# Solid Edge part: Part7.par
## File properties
Author: Vicky Raina
Template: Normal.par
Last saved by: MYPC
Revision: 8
Application: Solid Edge
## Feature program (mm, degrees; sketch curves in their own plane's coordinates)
sketch for "unnamed Protrusion 1" plane through (0, 0, 0) normal (0, 0, 1) x-axis (1, 0, 0)
  line (-37.8084, 8.3373) -> (-32.6389, -42.9666)
  arc centre (-23.6843, -42.0643) radius 9 from (-32.6389, -42.9666) to (-23.6843, -51.0643) ccw
  line (-23.6843, -51.0643) -> (23.6843, -51.0643)
  arc centre (23.6843, -42.0643) radius 9 from (32.6389, -42.9666) to (23.6843, -51.0643) cw
  line (37.8084, 8.3373) -> (32.6389, -42.9666)
  arc centre (27.8588, 9.3398) radius 10 from (37.8084, 8.3373) to (28.6379, 19.3094) ccw
  line (28.6379, 19.3094) -> (1.1687, 21.4561)
  arc centre (0, 6.5017) radius 15 from (-1.1687, 21.4561) to (1.1687, 21.4561) cw
  line (-28.6379, 19.3094) -> (-1.1687, 21.4561)
  arc centre (-27.8588, 9.3398) radius 10 from (-37.8084, 8.3373) to (-28.6379, 19.3094) cw
extrude "unnamed Protrusion 1" add finite 3.175 along +normal
sketch for "unnamed Protrusion 2" plane through (0, -15.2312, 3.175) normal (0, 0, 1) x-axis (1, 0, 0)
  circle centre (-23.6843, -26.8331) radius 6.5
extrude "unnamed Protrusion 2" add finite 4 along +normal
sketch for "unnamed Hole 1" plane through (-32.8919, -42.1766, 7.175) normal (0, 0, 1) x-axis (0, 1, 0)
  hole centre (0.1123, -9.2076) bore radius 3.5
hole "unnamed Hole 1" through
pattern "unnamed Pattern 1" of "unnamed Protrusion 2", "unnamed Hole 1"
pattern "unnamed Pattern 2"
sketch for "unnamed Protrusion 3" plane through (0, -15.2312, 3.175) normal (0, 0, 1) x-axis (1, 0, 0)
  circle centre (0.501, -0.9588) radius 10.5
extrude "unnamed Protrusion 3" add finite 3.175 along +normal
sketch for "unnamed Hole 2" plane through (0, -12.0628, 6.35) normal (0, 0, 1) x-axis (1, 0, 0)
  hole centre (0.501, -4.1271) bore radius 6
hole "unnamed Hole 2" through
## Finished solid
Body 1: solid body, 35 faces, 58 edges, 20 vertices.
  Faces by surface: cylinder 19, plane 16
  Edges by curve: circle 38, line 20
Bounding box of the edges (mm): 75.718 x 72.566 x 7.175, from (-37.8588, -51.0643, 0) to (37.8588, 21.5017, 7.175).
Cylindrical faces by radius (mm): R3.5 x4, R4.5 x4, R6 x1, R6.5 x4, R9 x2, R10 x2, R10.5 x1, R15 x1
Planar faces by outward normal: +z 10, -y 1, -z 1, oblique 4
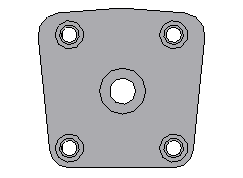
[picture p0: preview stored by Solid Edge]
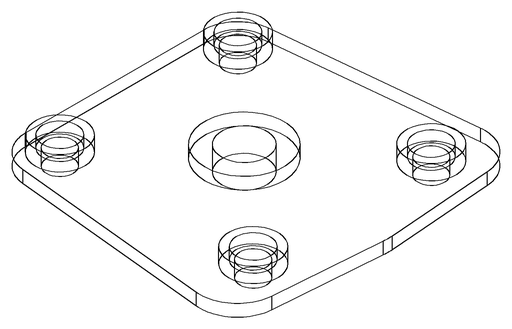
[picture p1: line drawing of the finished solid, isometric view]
